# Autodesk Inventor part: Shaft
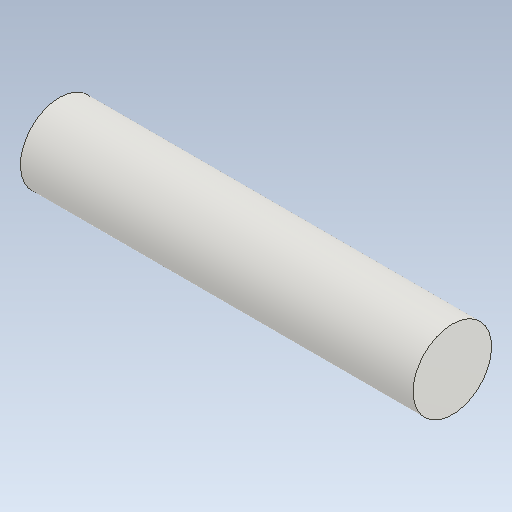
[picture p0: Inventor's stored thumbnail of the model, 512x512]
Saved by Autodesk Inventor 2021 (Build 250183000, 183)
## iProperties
Created: 2021-07
Part Number: Shaft
Material: Steel
Document SubType Name: Modeling
Designer: CHIRAG
Density: 1 g/cm^3
Appearance: Steel
CustomPartVersion: 1
Author: CHIRAG
Length: 150.000 mm
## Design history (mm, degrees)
sketch "Main Sketch"
  geometry: L1 (0, 0)-(150, 0) reference; L2 (0, 0)-(0, 15); L3 (150, 15)-(150, 0); L4 (0, 15)-(150, 15)
  constraints: 8 end point, 3 horizontal, 2 vertical
  dimensions: "d3" = 30 diameter of L4 L1 (derived)
revolve "Revolution1" sketch "Main Sketch" stored, may be unused: angle "d4" = 0 deg
body "Solid1"
other parameters: "d0" = 0, "d1" = 0, "d2" = 0, "Length" = 150 [user parameter]
